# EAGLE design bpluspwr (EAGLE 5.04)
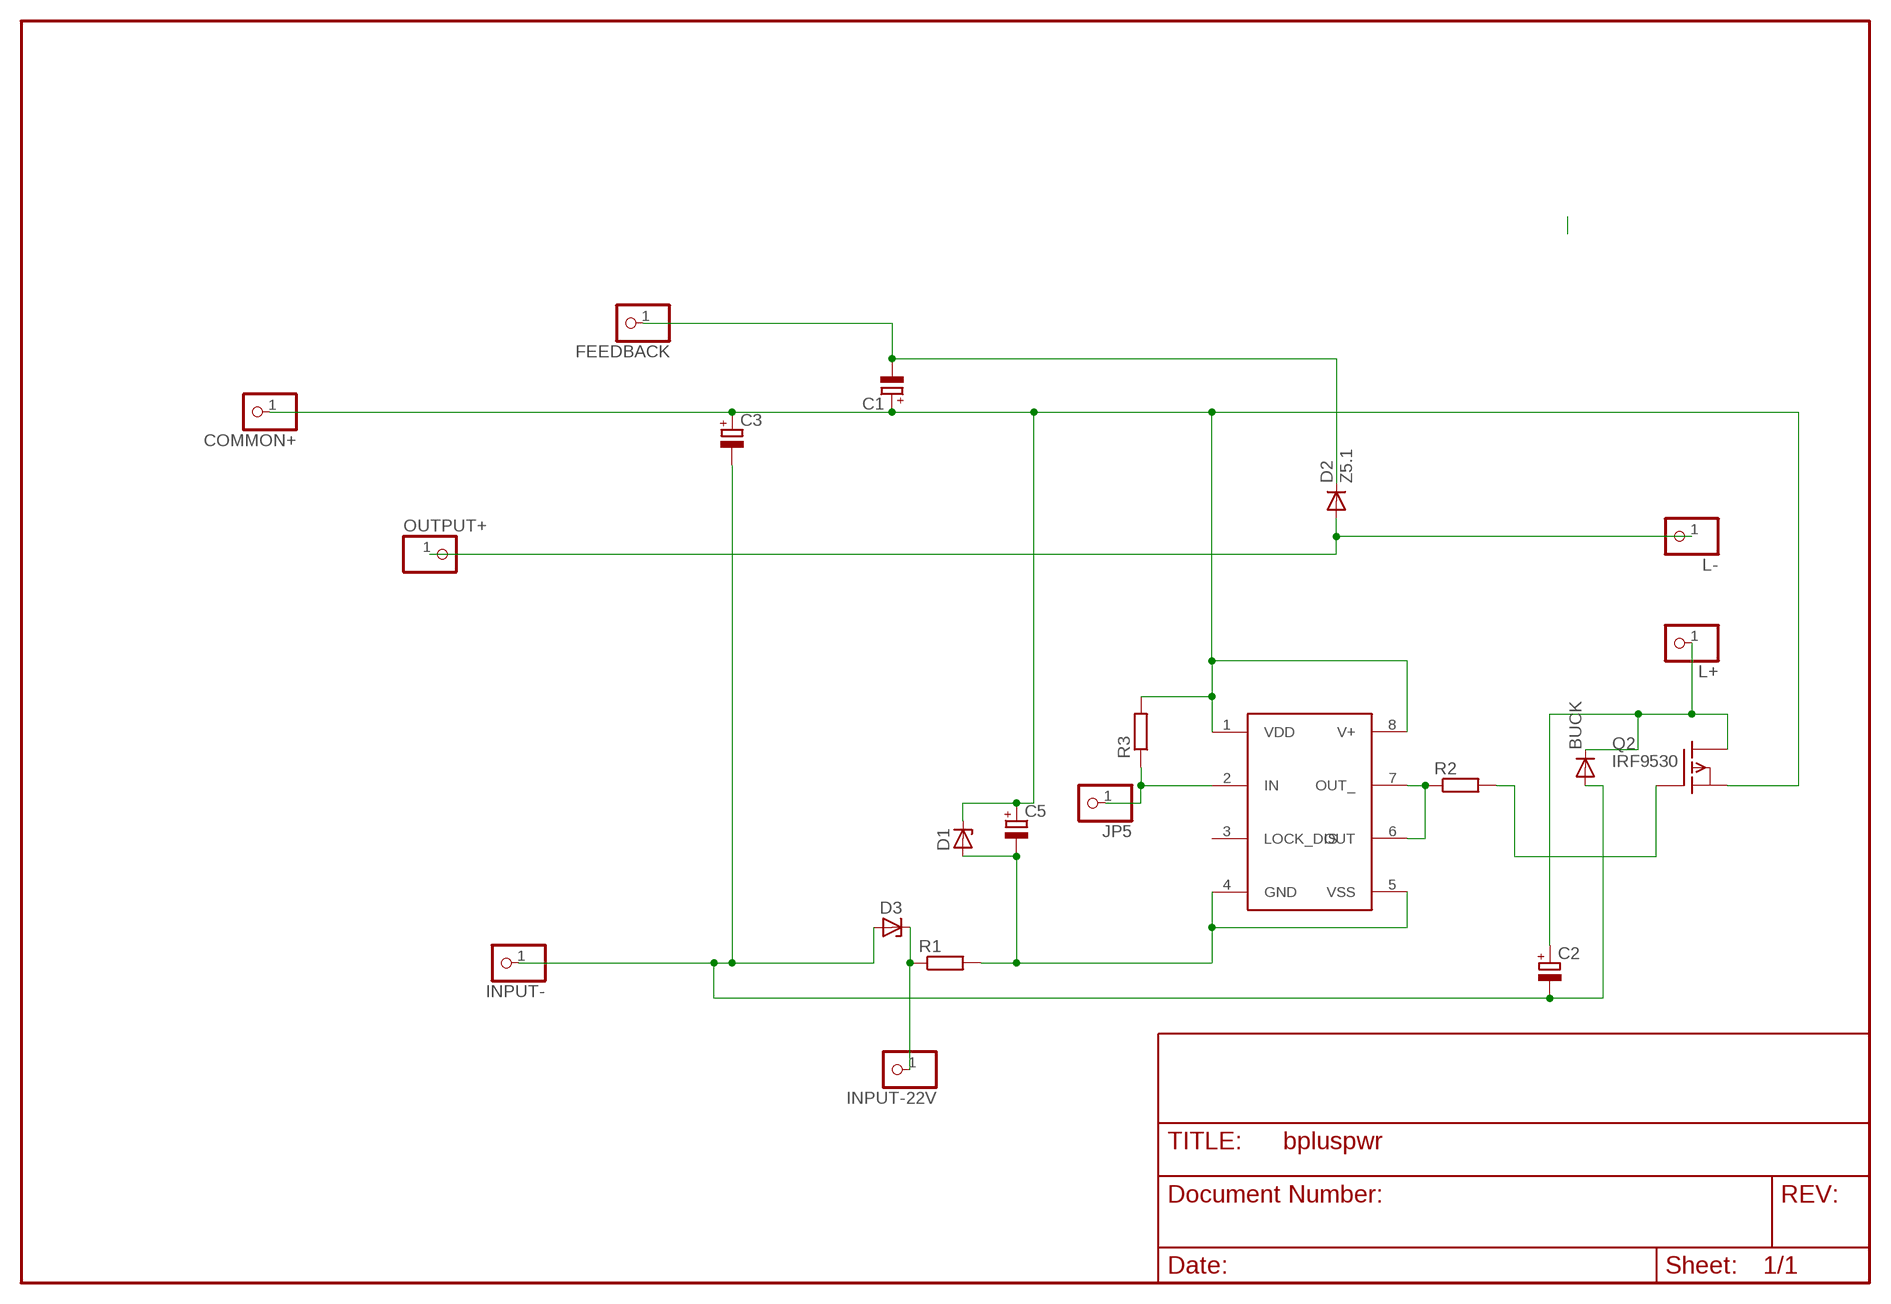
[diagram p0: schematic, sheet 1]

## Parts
BUCK  DIODE-D-5  [D-5]
C1  CPOL-EUE2.5-7  [E2,5-7]
C2  CPOL-EUE5-10.5  [E5-10,5]
C3  CPOL-EUE2-4  [E2-4]
C5  CPOL-EUE2-4  [E2-4]
COMMON+  PINHD-1X1  [1X01]
D1  ZENER-DIODEZD-2.5  [ZDIO-2.5]
D2  Z5.1  DIODE-D-2.5  [D-2.5]
D3  ZENER-DIODEZD-2.5  [ZDIO-2.5]
FEEDBACK  PINHD-1X1  [1X01]
IC1  TC4432X  [SO-08]
INPUT-  PINHD-1X1  [1X01]
INPUT-22V  PINHD-1X1  [1X01]
JP5  PINHD-1X1  [1X01]
L+  PINHD-1X1  [1X01]
L-  PINHD-1X1  [1X01]
OUTPUT+  PINHD-1X1  [1X01]
Q2  IRF9530  [TO220V]
R1  R-EU_0207/10  [0207/10]
R2  R-EU_R1206  [R1206]
R3  R-EU_R1206  [R1206]

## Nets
GND: C5.- D1.A IC1.4(GND) IC1.5(VSS) R1.2
N$1: IC1.2(IN) JP5.1 R3.1
N$2: C1.- D2.C FEEDBACK.1
N$3: IC1.6(OUT) IC1.7(OUT_) R2.1
N$5: D3.C INPUT-22V.1 R1.1
N$6: Q2.1(G) R2.2
N$9: BUCK.A C2.- C3.- D3.A INPUT-.1
N$10: BUCK.C C2.+ L+.1 Q2.2(D)
N$12: D2.A L-.1 OUTPUT+.1
VDD: C1.+ C3.+ C5.+ COMMON+.1 D1.C IC1.1(VDD) IC1.8(V+) Q2.3(S) R3.2
Unconnected: IC1.3(LOCK_DIS)

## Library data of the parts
BUCK D2 = diode:DIODE-: DIODE
C1-C3 C5 = rcl(2):CPOL-EU: POLARIZED CAPACITOR, European symbol
COMMON+ FEEDBACK INPUT- INPUT-22V JP5 L+ L- OUTPUT+ = pinhead:PINHD-1X1: PIN HEADER
D1 D3 = diode-1:ZENER-DIODE: Z-Diode
IC1 = microchip:TC4432
Q2 = transistor-fet:IRF9530: P-Channel Enhancement MOSFET (HEXFET); -100V; -12A; 0,3Ohm
R1-R3 = rcl-2:R-EU_: RESISTOR, European symbol

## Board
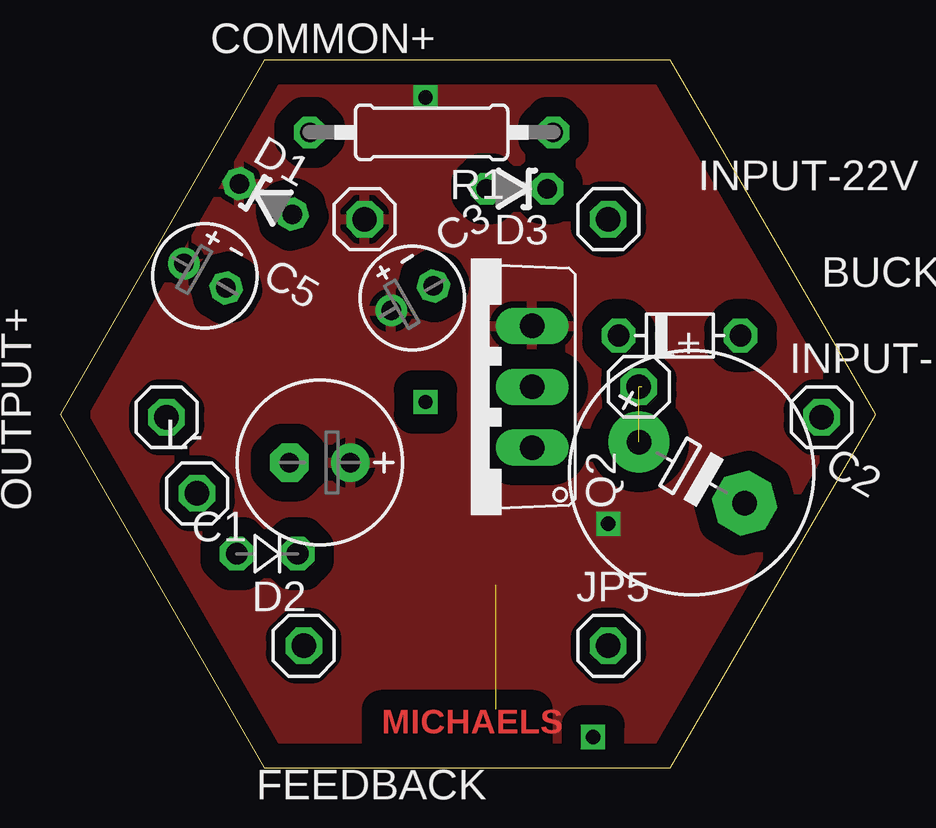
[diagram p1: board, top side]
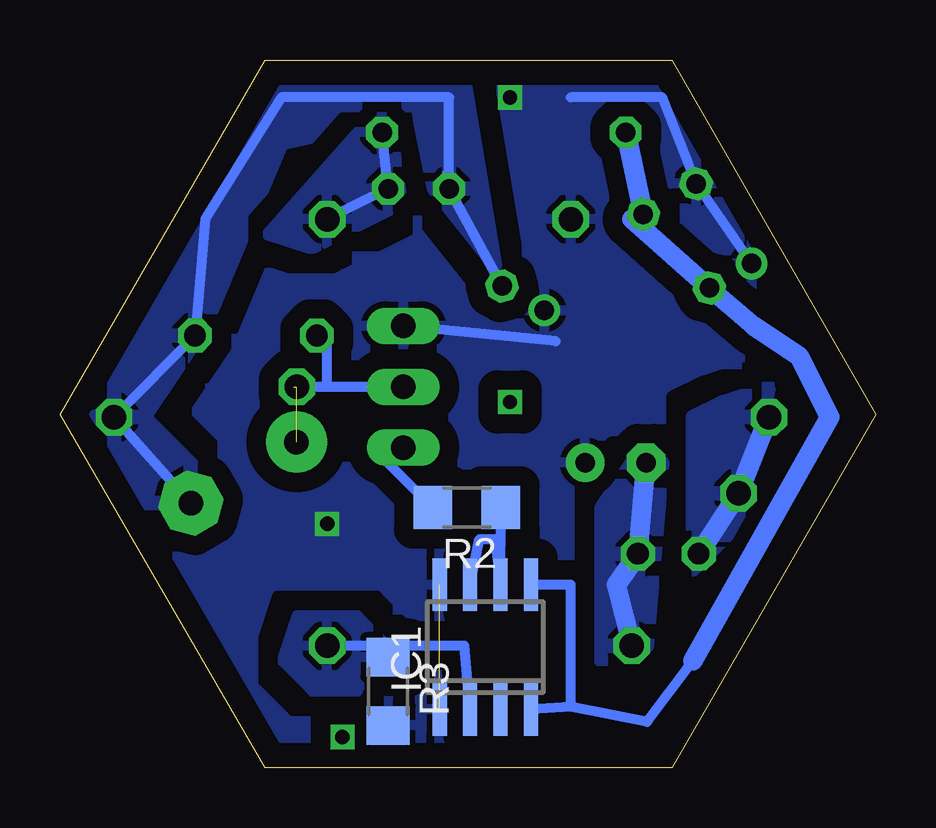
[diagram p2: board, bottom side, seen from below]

Size 34 x 29.5 mm. Coordinates in mm from the lower left corner, seen from the top.
Outline: 8.5,0 25.44,0 34,14.72 25.44,29.5 8.5,29.5 0,14.72 8.5,0
Copper layers (1*16): Top 0.035mm / dielectric 1.5mm / Bottom 0.035mm
Design rules "default": minimum track width 10mil, minimum drill 24mil, track to track 8mil, track to pad 8mil, pad to pad 8mil, via to via 8mil, smd to smd 8mil, copper to edge 40mil, drill to drill 8mil, minimum pad ring 10mil, minimum via ring 8mil, stop-mask expansion 4mil, vias tented up to drill 0mil, thermal gap 10mil

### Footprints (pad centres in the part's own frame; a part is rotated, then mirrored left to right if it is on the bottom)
D-5 = drill 0.9 octagon: A 2.54,0; C -2.54,0
E2,5-7 = drill 0.813 pad 1.6 round: + -1.27,0 | drill 0.813 pad 1.6 octagon: - 1.27,0
E5-10,5 = drill 1.016 pad 2.54 round: + -2.54,0 | drill 1.016 pad 2.54 octagon: - 2.54,0
E2-4 = drill 0.813 pad 1.27 round: + -1.016,0 | drill 0.813 pad 1.27 octagon: - 1.016,0
1X01 = drill 1.016 octagon: 1 0,0
ZDIO-2.5 = drill 0.813 octagon: A 1.27,0; C -1.27,0
D-2.5 = drill 0.9 octagon: A 1.27,0; C -1.27,0
SO-08 = smd 0.6 x 2.2: 1 -1.905,-2.6; 2 -0.635,-2.6; 3 0.635,-2.6; 4 1.905,-2.6; 5 1.905,2.6; 6 0.635,2.6; 7 -0.635,2.6; 8 -1.905,2.6
TO220V = drill 1.016 long: 1 -2.54,-2.54; 2 0,-2.54; 3 2.54,-2.54
0207/10 = drill 0.813 octagon: 1 -5.08,0; 2 5.08,0
R1206 = smd 1.6 x 1.803: 1 -1.422,0; 2 1.422,0

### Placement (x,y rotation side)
BUCK  25.83,18.01 0 top
C1  10.84,12.71 180 top
C2  26.34,12.3 330 top
C3  14.69,19.57 30 top
C5  6.04,20.51 330 top
COMMON+  12.7,22.86 0 top
D1  8.58,23.71 330 top
D2  8.64,8.91 180 top
D3  19.05,24.13 180 top
FEEDBACK  10.16,5.08 0 top
IC1  16.27,5.03 0 bottom
INPUT-  31.75,14.61 0 top
INPUT-22V  22.86,22.86 0 top
JP5  22.86,5.08 0 top
L+  24.13,15.88 0 top
L-  5.71,11.43 0 top
OUTPUT+  4.45,14.61 0 top
Q2  17.14,15.88 90 top
R1  15.49,26.48 180 top
R2  17.04,10.85 180 bottom
R3  20.32,3.17 270 bottom

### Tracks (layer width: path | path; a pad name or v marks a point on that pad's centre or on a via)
GND
  Bottom 0.406: IC1.5 12.7,7.62 12.7,2.54 | 12.7,2.54 IC1.4 | 10.16,22.86 D1.A | 7.62,4.45 9.53,1.91 12.7,2.54
  Bottom 0.813: 10.16,22.86 C5.- 5.08,18.41 3.17,17.14 1.91,14.61 7.62,4.45 | D1.A R1.2
N$1
  Bottom 0.406: JP5.1 17.14,5.08 IC1.2
  pour Bottom (isolate 0.406): 20.32,5.08 21.59,6.35 24.13,6.35 24.77,4.45 23.5,3.17 21.59,3.17 20.95,4.45
N$2
  Bottom 0.813: FEEDBACK.1 10.79,7.62 D2.C C1.-
  pour Bottom (isolate 0.61, rank 2): 10.16,12.7 11.43,10.79 11.43,4.45 9.53,5.08 8.89,12.7
N$3
  Bottom 0.406: R2.1 IC1.6 15.88,9.53 16.51,9.53 IC1.7
N$4  (via drill 0.6)
  other vias: 15.24,15.24
N$5
  Bottom 0.406: R1.1 D3.C INPUT-22V.1
  pour Bottom (isolate 0.406): 20.32,27.94 25.4,22.23 23.5,21.59 19.68,23.5
N$6
  Bottom 0.406: R2.2 20.32,12.7 Q2.1
N$8  (via drill 0.6)
  other vias: 22.23,1.27
N$9
  Bottom 0.406: D3.A 17.86,24.77 | C2.- INPUT-.1 BUCK.A 27.94,22.86 24.77,27.94 17.78,27.94 D3.A | C3.- D3.A
  pour Bottom (isolate 0.61, rank 2): 30.48,10.16 33.02,14.61 25.4,29.21 17.14,28.57 15.88,20.95 18.41,24.13 19.05,27.3 24.77,26.04 27.94,18.41 30.48,14.61 27.94,12.06
N$10  (2 unrouted)
  Bottom 0.406: Q2.2 22.86,15.88 | 22.86,15.88 24.26,15.88 | BUCK.C 22.86,18.01 22.86,15.88
N$12
  Bottom 0.813: OUTPUT+.1 L-.1 D2.A
  pour Bottom (isolate 0.61): 4.45,15.88 6.35,15.24 7.62,14.61 7.62,8.26 5.71,10.16
VDD  (via drill 0.6)  (1 unrouted)
  Bottom 0.406: 12.7,27.94 8.89,27.94 D1.C C5.+ | 13.34,17.78 Q2.3
  other vias: 15.24,27.94 22.86,10.16
  pour Bottom (isolate 0.813, rank 3): 10.16,29.21 25.4,29.84 33.66,14.61 25.4,0.64 8.89,0.64 0.64,14.61 8.89,29.21
  pour Top (isolate 0.813, rank 3): 10.16,29.21 25.4,29.84 33.66,14.61 25.4,0.64 8.89,0.64 0.64,14.61 8.89,29.21

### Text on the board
Top: MICHAELS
